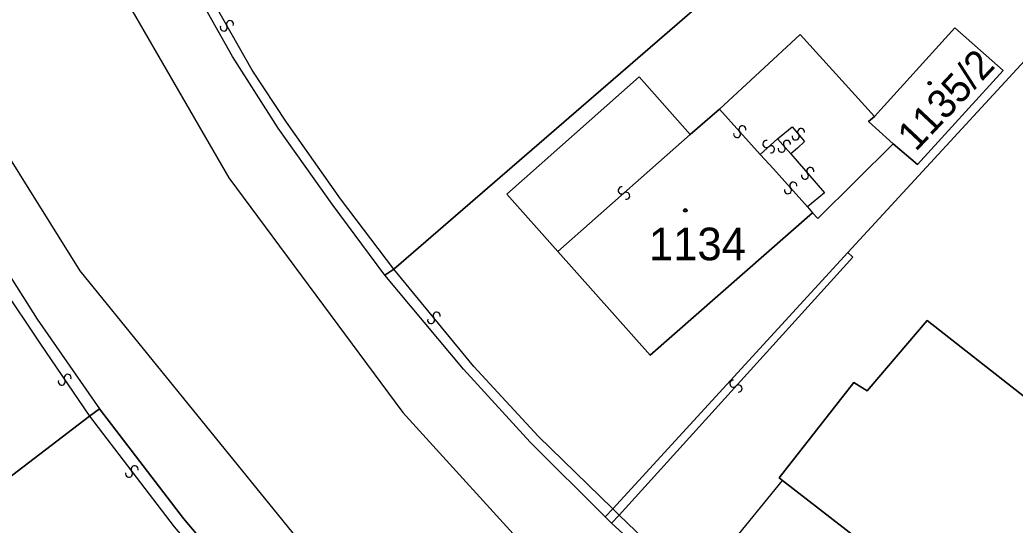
# Model space of a CAD drawing. Extents: x -600309 to -598967, y -1161267 to -1160292.
# Drawn here: x -599874.5 to -599822.6, y -1160562.3 to -1160536 of the extents above; entities that cross this region are included whole.
import ezdxf

# ---------------------------------------------------------------- set-up
doc = ezdxf.new("R2010")
doc.units = 0
for name, color, linetype in [('Level 1', 7, 'Continuous'), ('Level 13', 7, 'Continuous'), ('Level 3', 7, 'Continuous'), ('Level 4', 7, 'Continuous'), ('Level 5', 7, 'Continuous'), ('Level 60', 7, 'Continuous'), ('Vrstva 60', 7, 'Continuous')]:
    doc.layers.add(name, color=color, linetype=linetype)

msp = doc.modelspace()

# ---------------------------------------------------------------- linework, layer by layer
at = {"layer": 'Level 1'}
for points in [[(-599831.3, -1160548.11), (-599805.47, -1160520.1)], [(-599822.59, -1160520.97), (-599854.97, -1160548.99)], [(-599855.44, -1160549.29), (-599858.2, -1160545.6), (-599861.01, -1160541.63), (-599863.39, -1160537.9), (-599865.46, -1160534.21)], [(-599829.91, -1160541.02), (-599825.73, -1160536.41), (-599823.2, -1160538.63), (-599827.68, -1160543.53), (-599828.94, -1160542.45)], [(-599838, -1160540.64), (-599833.79, -1160536.76), (-599829.91, -1160541.02)], [(-599881.33, -1160539.22), (-599878.97, -1160542.95), (-599876.83, -1160546.48), (-599873.57, -1160551.59), (-599870.33, -1160556.26)], [(-599846.42, -1160548.06), (-599849.08, -1160545.08), (-599842.18, -1160538.96), (-599839.53, -1160541.97)], [(-599839.53, -1160541.97), (-599838, -1160540.64)], [(-599828.94, -1160542.45), (-599830.23, -1160541.29), (-599829.91, -1160541.02)], [(-599828.94, -1160542.45), (-599832.87, -1160546.34), (-599833.15, -1160546.05)], [(-599846.42, -1160548.06), (-599841.62, -1160553.46), (-599833.15, -1160546.05)], [(-599843.56, -1160561.48), (-599831.3, -1160548.11)], [(-599854.97, -1160548.99), (-599855.44, -1160549.29)], [(-599843.95, -1160561.89), (-599847.87, -1160558), (-599851.34, -1160554.19), (-599855.44, -1160549.29)], [(-599834.72, -1160560), (-599834.89, -1160559.86), (-599830.99, -1160554.9), (-599830.3, -1160555.33), (-599827.17, -1160551.66), (-599819.68, -1160557.53), (-599817.02, -1160554.65), (-599814.43, -1160552.21)], [(-599870.85, -1160556.65), (-599870.33, -1160556.26)], [(-599854.71, -1160574.1), (-599858.2, -1160570.68), (-599862.38, -1160566.2), (-599865.95, -1160561.98), (-599870.33, -1160556.26)], [(-599898.47, -1160577.75), (-599870.85, -1160556.65)], [(-599827.02, -1160571.61), (-599824.91, -1160567.59), (-599834.72, -1160560)], [(-599843.95, -1160561.89), (-599843.56, -1160561.48)], [(-599843.63, -1160562.23), (-599843.95, -1160561.89)], [(-599827.22, -1160572), (-599827.98, -1160571.59), (-599828.26, -1160571.84), (-599828.74, -1160572.13), (-599829.22, -1160572.31), (-599829.75, -1160572.41), (-599830.47, -1160572.39), (-599831.15, -1160572.2), (-599834.51, -1160569.85), (-599837.75, -1160567.28), (-599841.4, -1160564.25), (-599843.63, -1160562.23)]]:
    msp.add_lwpolyline(points, dxfattribs=at)
at = {"layer": 'Level 13'}
for centre, start, end in [((-599863.519, -1160536.21), 336.6097, 209.1997), ((-599863.841, -1160536.389), 156.8242, 28.9222), ((-599837.077, -1160541.942), 169.0918, 41.6818), ((-599836.802, -1160541.698), 349.3062, 221.4042), ((-599833.739, -1160541.831), 347.9119, 220.0099), ((-599835.551, -1160542.461), 79.0063, 311.1043), ((-599834.483, -1160542.456), 350.0512, 222.1492), ((-599834.02, -1160542.069), 167.6974, 40.2874), ((-599835.308, -1160542.738), 258.7918, 131.3818), ((-599834.756, -1160542.704), 169.8367, 42.4267), ((-599833.259, -1160543.872), 347.835, 219.933), ((-599833.541, -1160544.109), 167.6205, 40.2105), ((-599843.101, -1160544.881), 78.8459, 310.9439), ((-599834.428, -1160544.872), 168.97, 41.56), ((-599834.151, -1160544.628), 349.1845, 221.2825), ((-599842.859, -1160545.158), 258.6314, 131.2214), ((-599853.034, -1160551.636), 166.7975, 38.8955), ((-599852.747, -1160551.404), 346.5831, 219.1731), ((-599872.293, -1160554.853), 161.2628, 33.8528), ((-599871.986, -1160554.648), 341.4772, 213.5752), ((-599837.275, -1160554.955), 85.1649, 317.2629), ((-599837.004, -1160555.204), 264.9504, 137.5404), ((-599868.493, -1160559.419), 344.874, 216.972), ((-599868.787, -1160559.641), 164.6595, 37.2495)]:
    msp.add_arc(centre, 0.184, start, end, dxfattribs=at)
at = {"layer": 'Level 3'}
for points in [[(-599896.87, -1160478.15), (-599897.51, -1160478.88), (-599898.4, -1160481.47), (-599897.63, -1160484.52), (-599887.28, -1160503.28), (-599863.58, -1160544.22), (-599854.51, -1160556.46), (-599847.36, -1160564.3), (-599837.52, -1160572.8), (-599833.19, -1160575.14), (-599830.6, -1160576.31), (-599825.56, -1160578.13), (-599820.33, -1160581.49)], [(-599909.47, -1160487.96), (-599908.68, -1160487.64), (-599907.64, -1160487.55), (-599906.67, -1160487.79), (-599905.96, -1160488.23), (-599905.32, -1160488.94), (-599904.97, -1160489.58), (-599904.87, -1160490), (-599895.2, -1160507.68), (-599876.05, -1160541.59), (-599871.35, -1160549.07), (-599853.71, -1160570.79), (-599843.06, -1160580.97), (-599830.35, -1160588.89), (-599823.47, -1160592.45)], [(-599854.97, -1160548.99), (-599857.75, -1160545.32), (-599860.58, -1160541.32), (-599862.37, -1160538.62), (-599864.99, -1160533.98)], [(-599838, -1160540.64), (-599835.88, -1160543)], [(-599834.98, -1160542.2), (-599834.21, -1160541.57), (-599833.56, -1160542.33), (-599833.93, -1160542.68), (-599834.27, -1160542.97)], [(-599846.42, -1160548.06), (-599839.53, -1160541.97)], [(-599835.88, -1160543), (-599834.98, -1160542.2)], [(-599834.98, -1160542.2), (-599834.27, -1160542.97)], [(-599835.88, -1160543), (-599835.18, -1160543.75), (-599833.4, -1160545.74)], [(-599834.27, -1160542.97), (-599832.53, -1160545.01), (-599833.4, -1160545.74)], [(-599833.4, -1160545.74), (-599833.15, -1160546.05)], [(-599843.23, -1160561.8), (-599831.04, -1160548.36), (-599831.3, -1160548.11)], [(-599843.56, -1160561.48), (-599847.45, -1160557.69), (-599850.81, -1160554.05), (-599854.97, -1160548.99)], [(-599875.43, -1160549.85), (-599873.43, -1160552.84), (-599870.85, -1160556.65)], [(-599870.85, -1160556.65), (-599866.43, -1160562.41), (-599863.13, -1160566.26)], [(-599839.14, -1160565.44), (-599834.72, -1160560)], [(-599843.56, -1160561.48), (-599843.23, -1160561.8)], [(-599843.63, -1160562.23), (-599843.23, -1160561.8)], [(-599843.23, -1160561.8), (-599841.07, -1160563.88), (-599839.14, -1160565.44)]]:
    msp.add_lwpolyline(points, dxfattribs=at)
at = {"layer": 'Level 5'}
for centre, radius in [((-599827.04, -1160539.29), 0.09), ((-599827.04, -1160539.29), 0.0521), ((-599839.78, -1160545.92), 0.09), ((-599839.78, -1160545.92), 0.0521)]:
    msp.add_circle(centre, radius, dxfattribs=at)
at = {"layer": 'Level 60'}
for points in [[(-599843.56, -1160561.48), (-599843.95, -1160561.89), (-599847.87, -1160558), (-599851.34, -1160554.19), (-599855.44, -1160549.29), (-599854.97, -1160548.99), (-599822.59, -1160520.97), (-599805.47, -1160520.1), (-599831.3, -1160548.11)], [(-599825.73, -1160536.41), (-599829.91, -1160541.02), (-599833.79, -1160536.76), (-599838, -1160540.64), (-599839.53, -1160541.97), (-599842.18, -1160538.96), (-599849.08, -1160545.08), (-599846.42, -1160548.06), (-599841.62, -1160553.46), (-599833.15, -1160546.05), (-599832.87, -1160546.34), (-599828.94, -1160542.45), (-599827.68, -1160543.53), (-599823.2, -1160538.63)], [(-599829.91, -1160541.02), (-599825.73, -1160536.41), (-599823.2, -1160538.63), (-599827.68, -1160543.53), (-599828.94, -1160542.45), (-599830.23, -1160541.29)], [(-599830.23, -1160541.29), (-599828.94, -1160542.45), (-599832.87, -1160546.34), (-599833.15, -1160546.05), (-599841.62, -1160553.46), (-599846.42, -1160548.06), (-599849.08, -1160545.08), (-599842.18, -1160538.96), (-599839.53, -1160541.97), (-599838, -1160540.64), (-599833.79, -1160536.76), (-599829.91, -1160541.02)], [(-599910.32, -1160572.73), (-599910.35, -1160572.03), (-599910.7, -1160557.35), (-599881.69, -1160539.44), (-599881.33, -1160539.22), (-599878.97, -1160542.95), (-599876.83, -1160546.48), (-599873.57, -1160551.59), (-599870.33, -1160556.26), (-599870.85, -1160556.65), (-599898.47, -1160577.75)], [(-599814.59, -1160569.28), (-599817.32, -1160573.57), (-599819.05, -1160576.97), (-599827.22, -1160572), (-599827.02, -1160571.61), (-599824.91, -1160567.59), (-599834.72, -1160560), (-599834.89, -1160559.86), (-599830.99, -1160554.9), (-599830.3, -1160555.33), (-599827.17, -1160551.66), (-599819.68, -1160557.53), (-599817.02, -1160554.65), (-599814.43, -1160552.21), (-599806.63, -1160559.73), (-599810.84, -1160564.32)], [(-599854.71, -1160574.1), (-599855.2, -1160574.6), (-599870.1, -1160589.88), (-599890.32, -1160581.26), (-599890.79, -1160581.05), (-599898.47, -1160577.75), (-599870.85, -1160556.65), (-599870.33, -1160556.26), (-599865.95, -1160561.98), (-599862.38, -1160566.2), (-599858.2, -1160570.68)]]:
    msp.add_lwpolyline(points, close=True, dxfattribs=at)
for points in [[(-599819.68, -1160557.53), (-599827.17, -1160551.66), (-599830.3, -1160555.33), (-599830.99, -1160554.9), (-599834.89, -1160559.86), (-599834.72, -1160560), (-599824.91, -1160567.59), (-599827.02, -1160571.61), (-599827.22, -1160572), (-599827.98, -1160571.59), (-599828.26, -1160571.84), (-599828.74, -1160572.13), (-599829.22, -1160572.31), (-599829.75, -1160572.41), (-599830.47, -1160572.39), (-599831.15, -1160572.2), (-599834.51, -1160569.85), (-599837.75, -1160567.28), (-599841.4, -1160564.25), (-599843.63, -1160562.23), (-599843.95, -1160561.89), (-599843.56, -1160561.48), (-599831.3, -1160548.11), (-599805.47, -1160520.1)], [(-599822.59, -1160520.97), (-599854.97, -1160548.99), (-599855.44, -1160549.29), (-599858.2, -1160545.6), (-599861.01, -1160541.63), (-599863.39, -1160537.9), (-599865.46, -1160534.21)]]:
    msp.add_lwpolyline(points, dxfattribs=at)
at = {"layer": 'Vrstva 60'}
for points in [[(-599912.7, -1160482.51), (-599909.47, -1160487.96), (-599906.88, -1160492.33), (-599892.13, -1160519.12), (-599881.33, -1160539.22), (-599878.97, -1160542.95), (-599876.83, -1160546.48), (-599873.57, -1160551.59), (-599870.33, -1160556.26), (-599865.95, -1160561.98), (-599862.38, -1160566.2), (-599858.2, -1160570.68), (-599854.71, -1160574.1), (-599854.51, -1160574.29), (-599850.48, -1160577.68), (-599845.43, -1160581.65), (-599840.41, -1160585.36), (-599834.68, -1160589.3), (-599829.67, -1160592.37), (-599825.35, -1160594.88), (-599824.4, -1160595.69), (-599823.47, -1160592.45), (-599820.33, -1160581.49)], [(-599841.4, -1160564.25), (-599843.63, -1160562.23), (-599843.95, -1160561.89), (-599847.87, -1160558), (-599851.34, -1160554.19), (-599855.44, -1160549.29), (-599858.2, -1160545.6), (-599861.01, -1160541.63), (-599863.39, -1160537.9), (-599865.46, -1160534.21), (-599868.36, -1160528.92), (-599871.23, -1160523.67), (-599874.2, -1160518.44), (-599877.03, -1160513.42), (-599882.89, -1160502.71), (-599892.9, -1160484.74)]]:
    msp.add_lwpolyline(points, dxfattribs=at)

# ---------------------------------------------------------------- texts
at = {"layer": 'Level 4'}
msp.add_text('1135/2', height=1.5, rotation=46.8, dxfattribs=at).set_placement((-599827.762, -1160542.897))
msp.add_text('1134', height=1.7, dxfattribs=at).set_placement((-599841.675, -1160548.52))

doc.saveas('drawing.dxf')
